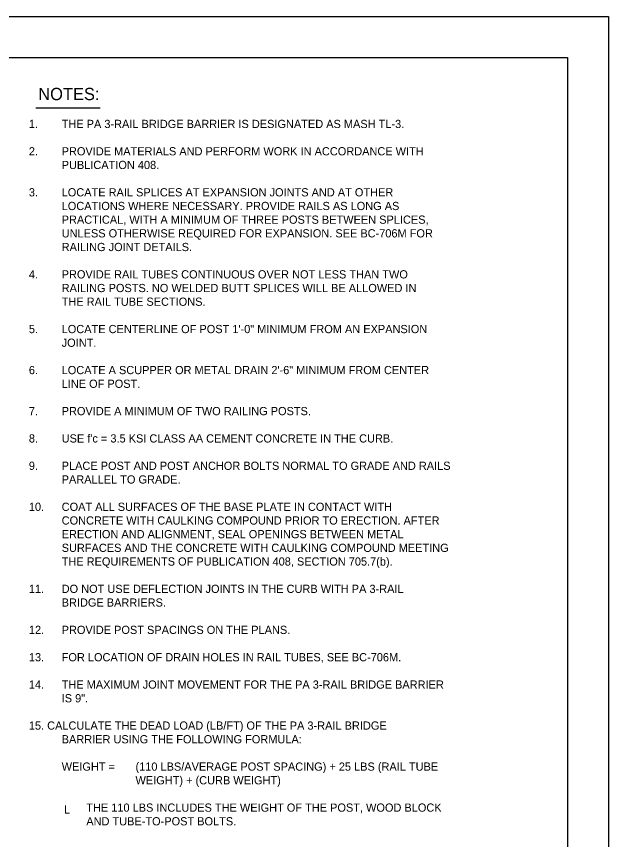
# Model space of a CAD drawing. Extents: x 641054 to 641910, y 298137 to 299325.
# Drawn here: x 641679 to 641895.5, y 299024.4 to 299325.4 of the extents above; entities that cross this region are included whole.
import ezdxf

# ---------------------------------------------------------------- set-up
doc = ezdxf.new("R2010")
doc.units = 0
doc.layers.add('2', color=7, linetype='Continuous')
doc.layers.add('PLT-BNDY', color=7, linetype='Continuous')

msp = doc.modelspace()

# ---------------------------------------------------------------- linework, layer by layer
at = {"layer": '2'}
for p, q in [((641094.49, 299310.38), (641880.49, 299310.38)), ((641880.49, 299310.38), (641880.49, 298746.38)), ((641686.02, 299292.02), (641709.62, 299292.02))]:
    msp.add_line(p, q, dxfattribs=at)
at = {"layer": 'PLT-BNDY'}
msp.add_lwpolyline([(641054.49, 299325.38), (641895.49, 299325.38), (641895.49, 298731.38), (641054.49, 298731.38)], close=True, dxfattribs=at)

# ---------------------------------------------------------------- texts
at = {"layer": '2'}
for s, height, p in [('NOTES:', 4.5, (641686.92, 299294.78)), ('1.', 3, (641683.49, 299284.58)), ('THE PA 3-RAIL BRIDGE BARRIER IS DESIGNATED AS MASH TL-3.', 3, (641695.49, 299284.58)), ('2.', 3, (641683.49, 299274.58)), ('PROVIDE MATERIALS AND PERFORM WORK IN ACCORDANCE WITH ', 3, (641695.49, 299274.58)), ('PUBLICATION 408.', 3, (641695.49, 299269.58)), ('3.', 3, (641683.49, 299259.58)), ('LOCATE RAIL SPLICES AT EXPANSION JOINTS AND AT OTHER ', 3, (641695.49, 299259.58)), ('LOCATIONS WHERE NECESSARY. PROVIDE RAILS AS LONG AS ', 3, (641695.49, 299254.58)), ('PRACTICAL, WITH A MINIMUM OF THREE POSTS BETWEEN SPLICES, ', 3, (641695.49, 299249.58)), ('UNLESS OTHERWISE REQUIRED FOR EXPANSION. SEE BC-706M FOR ', 3, (641695.49, 299244.58)), ('RAILING JOINT DETAILS.', 3, (641695.49, 299239.58)), ('4.', 3, (641683.49, 299229.58)), ('PROVIDE RAIL TUBES CONTINUOUS OVER NOT LESS THAN TWO ', 3, (641695.49, 299229.58)), ('RAILING POSTS. NO WELDED BUTT SPLICES WILL BE ALLOWED IN ', 3, (641695.49, 299224.58)), ('THE RAIL TUBE SECTIONS.', 3, (641695.49, 299219.58)), ('5.', 3, (641683.49, 299209.58)), ('LOCATE CENTERLINE OF POST 1\'-0" MINIMUM FROM AN EXPANSION ', 3, (641695.49, 299209.58)), ('JOINT.', 3, (641695.49, 299204.58)), ('6.', 3, (641683.49, 299194.58)), ('LOCATE A SCUPPER OR METAL DRAIN 2\'-6" MINIMUM FROM CENTER ', 3, (641695.49, 299194.58)), ('LINE OF POST.', 3, (641695.49, 299189.58)), ('7.', 3, (641683.49, 299179.58)), ('PROVIDE A MINIMUM OF TWO RAILING POSTS.', 3, (641695.49, 299179.58)), ('8.', 3, (641683.49, 299169.58)), ("USE f'c = 3.5 KSI CLASS AA CEMENT CONCRETE IN THE CURB.", 3, (641695.49, 299169.58)), ('9.', 3, (641683.49, 299159.58)), ('PLACE POST AND POST ANCHOR BOLTS NORMAL TO GRADE AND RAILS ', 3, (641695.49, 299159.58)), ('PARALLEL TO GRADE.', 3, (641695.49, 299154.58)), ('10.', 3, (641683.49, 299144.58)), ('COAT ALL SURFACES OF THE BASE PLATE IN CONTACT WITH ', 3, (641695.49, 299144.58)), ('CONCRETE WITH CAULKING COMPOUND PRIOR TO ERECTION. AFTER ', 3, (641695.49, 299139.58)), ('ERECTION AND ALIGNMENT, SEAL OPENINGS BETWEEN METAL ', 3, (641695.49, 299134.58)), ('SURFACES AND THE CONCRETE WITH CAULKING COMPOUND MEETING ', 3, (641695.49, 299129.58)), ('THE REQUIREMENTS OF PUBLICATION 408, SECTION 705.7(b).', 3, (641695.49, 299124.58)), ('11.', 3, (641683.49, 299114.58)), ('DO NOT USE DEFLECTION JOINTS IN THE CURB WITH PA 3-RAIL ', 3, (641695.49, 299114.58)), ('BRIDGE BARRIERS.', 3, (641695.49, 299109.58)), ('12.', 3, (641683.49, 299099.58)), ('PROVIDE POST SPACINGS ON THE PLANS.', 3, (641695.49, 299099.58)), ('13.', 3, (641683.49, 299089.58)), ('FOR LOCATION OF DRAIN HOLES IN RAIL TUBES, SEE BC-706M.', 3, (641695.49, 299089.58)), ('14.', 3, (641683.49, 299079.58)), ('THE MAXIMUM JOINT MOVEMENT FOR THE PA 3-RAIL BRIDGE BARRIER ', 3, (641695.49, 299079.58)), ('IS 9".', 3, (641695.49, 299074.58)), ('15. CALCULATE THE DEAD LOAD (LB/FT) OF THE PA 3-RAIL BRIDGE ', 3, (641683.49, 299064.58)), ('BARRIER USING THE FOLLOWING FORMULA:', 3, (641695.49, 299059.58)), ('WEIGHT =', 3, (641695.49, 299049.58)), ('(110 LBS/AVERAGE POST SPACING) + 25 LBS (RAIL TUBE ', 3, (641722.49, 299049.58)), ('WEIGHT) + (CURB WEIGHT)', 3, (641722.49, 299044.58)), ('L', 3, (641696.36, 299033.89)), ('THE 110 LBS INCLUDES THE WEIGHT OF THE POST, WOOD BLOCK ', 3, (641704.49, 299034.58)), ('AND TUBE-TO-POST BOLTS.', 3, (641704.49, 299029.58))]:
    msp.add_text(s, height=height, dxfattribs=at).set_placement(p)

doc.saveas('drawing.dxf')
